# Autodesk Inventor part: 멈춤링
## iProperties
Created: 2014-12
Part Number: 멈춤링
Material: 강, 연강
Description: 리테이닝 링(C형)
Document SubType Name: Modeling
Standard: KS B 1336
Designer: KYOUNG IL JANG
Standards Organization: KS
Language: ko-KR
Size Designation: 17 x 1
Categories: <MemberInstance><Categories><Category DisplayName="샤프트 부품" InternalName="7f7aeb1f-a693-4053-b835-cee3144e0d98" Mnemonic="SHFT"><Category DisplayName="써클립" Inter
Density: 7.86 g/cm^3
Mass: 0.979804 g
Surface Area: 3.83537 cm^2
Volume: 0.124657 cm^3
Company: 한국ATC센터
Author: KYOUNG IL JANG
IsCustomPart: 0
